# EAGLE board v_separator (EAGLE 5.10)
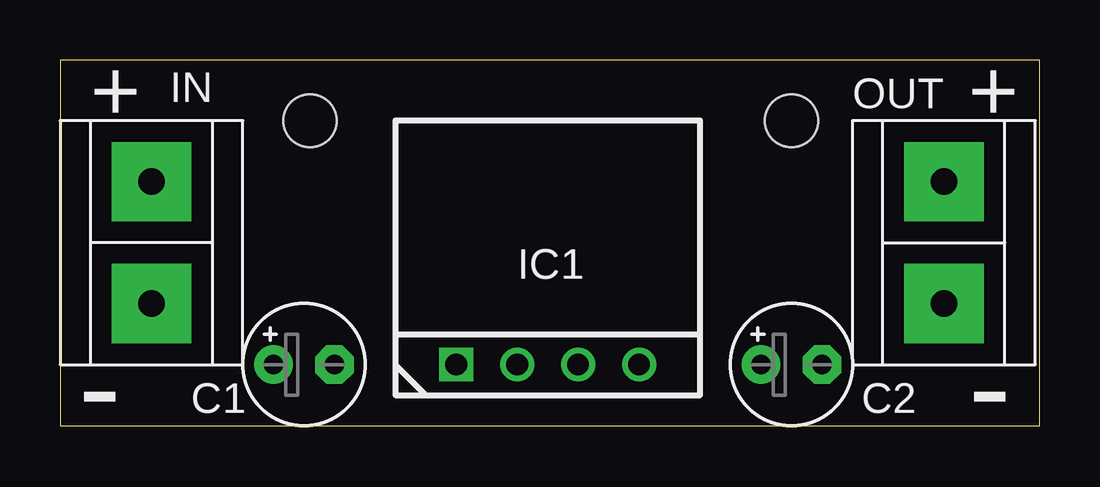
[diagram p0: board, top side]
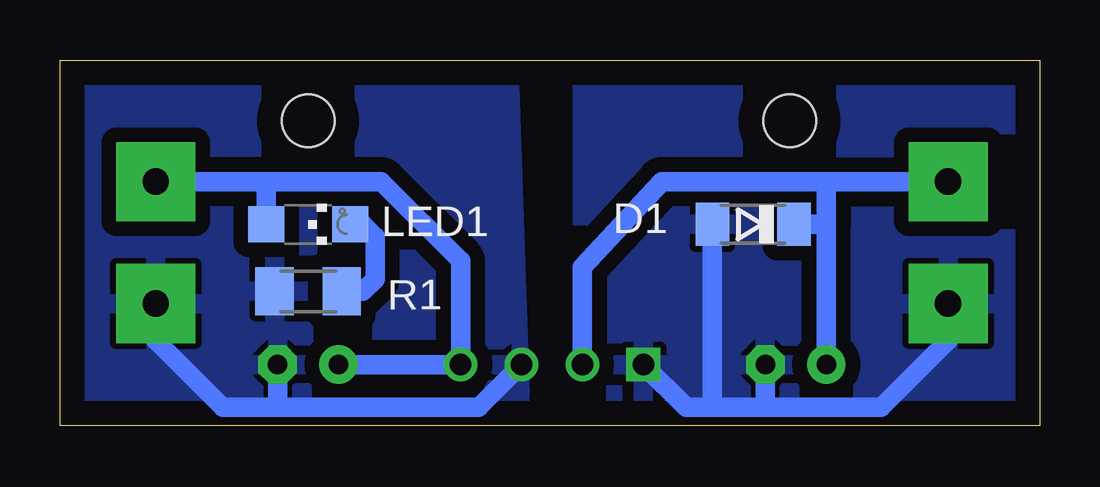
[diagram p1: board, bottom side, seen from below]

Size 40.82 x 15.23 mm. Coordinates in mm from the lower left corner, seen from the top.
Outline: 0,0 40.82,0 40.82,15.23 0,15.23 0,0
Copper layers (1*16): Top 0.035mm / dielectric 1.5mm / Bottom 0.035mm
Design rules "default": minimum track width 10mil, minimum drill 24mil, track to track 8mil, track to pad 8mil, pad to pad 8mil, via to via 8mil, smd to smd 8mil, copper to edge 40mil, drill to drill 8mil, minimum pad ring 10mil, minimum via ring 8mil, stop-mask expansion 4mil, vias tented up to drill 0mil, thermal gap 10mil
Holes 2.2 mm at 10.41,12.7 30.48,12.7

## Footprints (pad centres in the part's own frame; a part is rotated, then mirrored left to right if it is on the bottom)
E2,5-5 = drill 0.813 pad 1.6 round: + -1.27,0 | drill 0.813 pad 1.6 octagon: - 1.27,0
SOD80C = smd 1.4 x 1.8: A 1.7,0; C -1.7,0
QDC1S_H = drill 0.9 square: 1 -3.81,0 | drill 0.9 round: 2 -1.27,0; 3 1.27,0; 4 3.81,0
ARK500/2 = drill 1.1 pad 3.302 square: 1 -2.54,0; 2 2.54,0
CHIPLED_1206 = smd 1.5 x 1.5: A 0,-1.75; C 0,1.75
M1206 = smd 1.6 x 2: 1 -1.4,0; 2 1.4,0

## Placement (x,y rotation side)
C1  47/35  [E2,5-5]  10.16,2.54 0 top
C2  100/25  [E2,5-5]  30.48,2.54 0 top
D1  BAS85  [SOD80C]  11.94,8.38 180 bottom
IC1  QDC1S  [QDC1S_H]  20.32,2.54 0 top
IN  ARK500/2  [ARK500/2]  3.81,7.62 270 top
LED1  [CHIPLED_1206]  30.48,8.38 270 bottom
OUT  ARK500/2  [ARK500/2]  36.83,7.62 90 top
R1  1k  [M1206]  30.48,5.59 180 bottom

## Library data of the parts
C1 C2 R1 = rcl
D1 = diode
IC1 = QDC1S
IN OUT = DS
LED1 = led

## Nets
GND: C1.- D1.A IC1.1 IN.2
N$1: C1.+ D1.C IC1.2 IN.1
N$3: LED1.C R1.1
N$7: C2.+ IC1.4 LED1.A OUT.2
V0: C2.- IC1.3 OUT.1 R1.2

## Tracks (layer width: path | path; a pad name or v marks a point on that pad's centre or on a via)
GND
  Bottom 0.813: IN.2 3.81,3.56 6.6,0.76 11.43,0.76 | 11.43,0.76 13.46,0.76 | 13.46,0.76 14.73,0.76 IC1.1 | 11.43,0.76 C1.- | D1.A 13.64,0.94 13.46,0.76
  pour Bottom (isolate 0.61): 0,16.51 19.05,15.24 19.05,0 0,0
N$1
  Bottom 0.813: 8.89,10.16 IN.1 | 8.89,10.16 15.75,10.16 19.05,6.6 IC1.2 | C1.+ 8.89,8.38 | 8.89,8.38 8.89,10.16 | 8.89,8.38 D1.C
N$3
  Bottom 0.813: LED1.C 28.19,8.38 27.69,7.87 27.69,6.1 28.19,5.59 R1.1
N$7
  Bottom 0.813: 32.51,10.16 27.43,10.16 24.13,6.86 IC1.4 C2.+ | 32.51,10.16 OUT.2 | LED1.A 32.23,9.88 32.51,10.16
V0
  Bottom 0.813: OUT.1 36.83,3.56 34.04,0.76 32,0.76 | 32,0.76 23.37,0.76 IC1.3 | C2.- 31.75,1.02 32,0.76
  pour Bottom (isolate 0.61): 22.1,14.73 21.59,0 40.64,0 40.89,14.99

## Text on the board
tPlace: + | + | - | -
